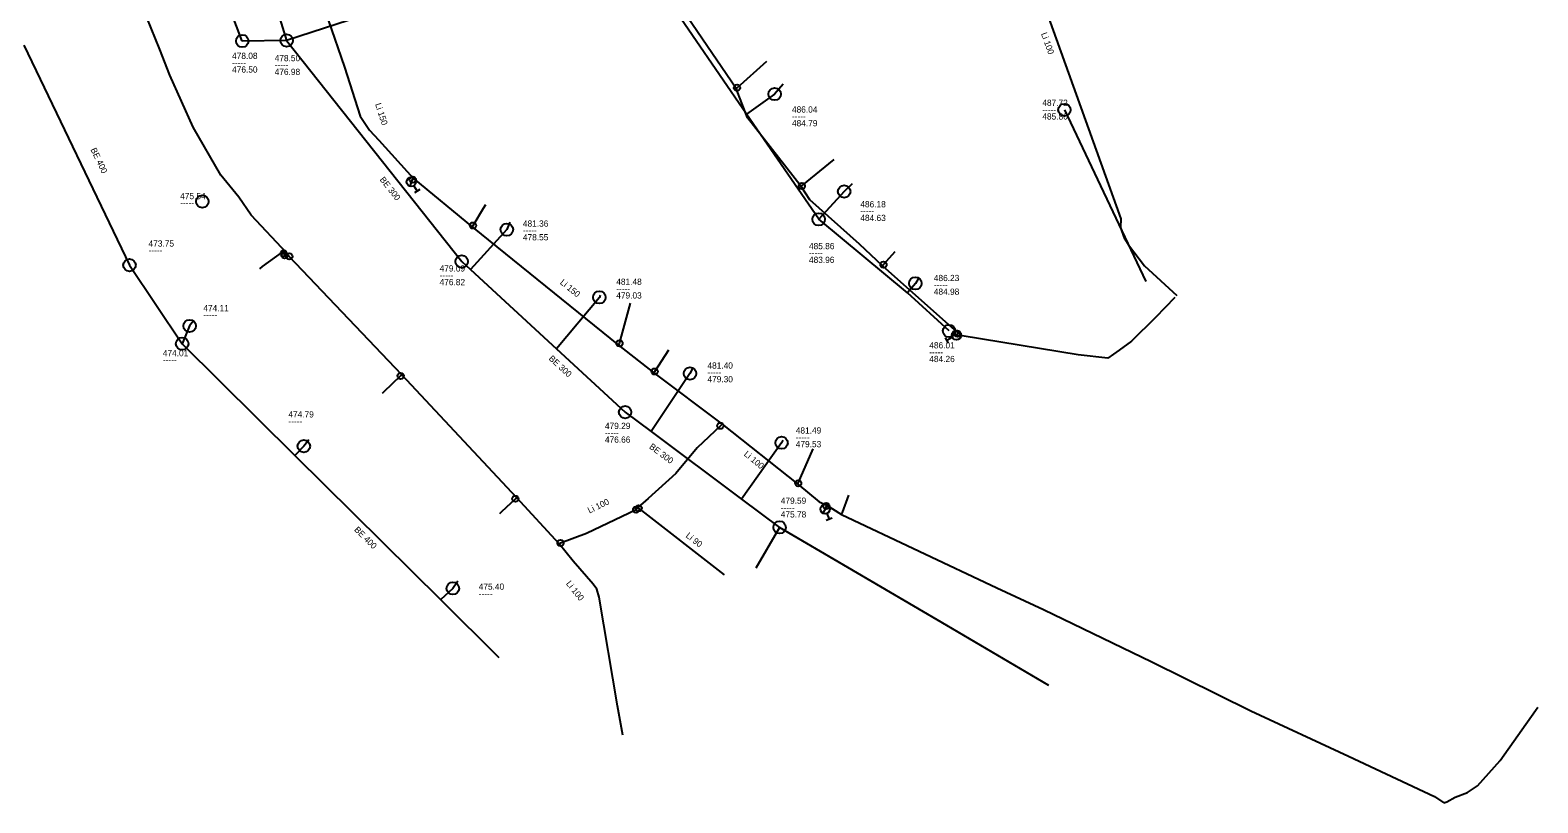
# Model space of a CAD drawing. Extents: x -685576 to -685179, y -1163336 to -1162895.
# Drawn here: x -685424.5 to -685182.3, y -1163335.7 to -1163211.6 of the extents above; entities that cross this region are included whole.
import ezdxf

# ---------------------------------------------------------------- set-up
doc = ezdxf.new("R2010")
doc.units = 0
doc.layers.add('Level 0', color=7, linetype='Continuous')

msp = doc.modelspace()

# ---------------------------------------------------------------- linework, layer by layer
at = {"layer": 'Level 0'}
for p, q in [((-685390.47, -1163213.33), (-685406.53, -1163170.83)), ((-685269.88, -1163184.54), (-685249.32, -1163241.89)), ((-685389.45, -1163193.49), (-685383.34, -1163213.24)), ((-685309.45, -1163225.05), (-685329.26, -1163196.15)), ((-685346.32, -1163201.19), (-685383.34, -1163213.24)), ((-685311.11, -1163220.95), (-685322.31, -1163204.53)), ((-685403.73, -1163214.71), (-685406.47, -1163207.84)), ((-685376.64, -1163209.9), (-685374.03, -1163217.52)), ((-685425.56, -1163214), (-685408.59, -1163249.33)), ((-685402.13, -1163218.81), (-685403.73, -1163214.71)), ((-685383.34, -1163213.24), (-685390.47, -1163213.33)), ((-685383.34, -1163213.24), (-685355.21, -1163248.74)), ((-685374.03, -1163217.52), (-685371.51, -1163225.37)), ((-685310.97, -1163220.83), (-685306.17, -1163216.55)), ((-685398.38, -1163227.18), (-685402.13, -1163218.81)), ((-685311.11, -1163220.95), (-685310.97, -1163220.83)), ((-685309.3, -1163225.68), (-685311.11, -1163220.95)), ((-685304.94, -1163221.85), (-685309.45, -1163225.05)), ((-685303.56, -1163220.24), (-685304.94, -1163221.85)), ((-685258.38, -1163224.39), (-685245.28, -1163251.95)), ((-685393.89, -1163234.85), (-685398.38, -1163227.18)), ((-685371.51, -1163225.37), (-685370.03, -1163227.64)), ((-685297.86, -1163241.96), (-685309.45, -1163225.05)), ((-685300.66, -1163236.72), (-685309.3, -1163225.68)), ((-685370.03, -1163227.64), (-685368.52, -1163229.24)), ((-685368.52, -1163229.24), (-685362.98, -1163235.41)), ((-685300.57, -1163236.6), (-685295.39, -1163232.34)), ((-685391.01, -1163238.41), (-685393.89, -1163234.85)), ((-685363.05, -1163235.25), (-685363.57, -1163236.66)), ((-685363.08, -1163235.58), (-685363.31, -1163235.95)), ((-685362.98, -1163235.41), (-685363.08, -1163235.58)), ((-685362.98, -1163235.41), (-685353.47, -1163243.25)), ((-685362.91, -1163236.59), (-685362.39, -1163237.44)), ((-685300.66, -1163236.72), (-685300.57, -1163236.6)), ((-685299.28, -1163238.81), (-685300.66, -1163236.72)), ((-685292.49, -1163236.25), (-685293.76, -1163237.5)), ((-685389.06, -1163241.28), (-685391.01, -1163238.41)), ((-685361.96, -1163237.17), (-685362.81, -1163237.7)), ((-685291.29, -1163245.96), (-685299.28, -1163238.81)), ((-685293.76, -1163237.5), (-685297.86, -1163241.96)), ((-685383.31, -1163247.4), (-685389.06, -1163241.28)), ((-685353.38, -1163242.96), (-685351.69, -1163240.16)), ((-685351.69, -1163240.16), (-685351.34, -1163239.61)), ((-685283.57, -1163253.78), (-685297.86, -1163241.96)), ((-685249.32, -1163241.89), (-685249.35, -1163243.29)), ((-685347.96, -1163243.62), (-685353.8, -1163250.04)), ((-685353.47, -1163243.25), (-685353.38, -1163242.96)), ((-685353.47, -1163243.25), (-685330.04, -1163262.19)), ((-685347.49, -1163242.45), (-685347.96, -1163243.62)), ((-685249.35, -1163243.29), (-685248.84, -1163244.81)), ((-685287.62, -1163249.46), (-685291.29, -1163245.96)), ((-685248.84, -1163244.81), (-685248.06, -1163246.08)), ((-685248.06, -1163246.08), (-685245.49, -1163249.43)), ((-685384.01, -1163247.19), (-685387.27, -1163249.55)), ((-685383.83, -1163247.45), (-685384.01, -1163247.19)), ((-685383.57, -1163247.66), (-685383.83, -1163247.45)), ((-685383.67, -1163247.77), (-685383.57, -1163247.66)), ((-685383.57, -1163247.66), (-685383.31, -1163247.4)), ((-685383.31, -1163247.4), (-685382.91, -1163247.92)), ((-685364.83, -1163266.94), (-685382.91, -1163247.92)), ((-685355.21, -1163248.74), (-685353.8, -1163250.04)), ((-685287.45, -1163249.24), (-685285.59, -1163247.15)), ((-685408.59, -1163249.33), (-685400.12, -1163261.95)), ((-685387.27, -1163249.55), (-685387.72, -1163249.9)), ((-685353.8, -1163250.04), (-685340, -1163262.77)), ((-685287.62, -1163249.46), (-685287.45, -1163249.24)), ((-685275.49, -1163260.19), (-685287.62, -1163249.46)), ((-685281.86, -1163251.51), (-685282.33, -1163252.26)), ((-685245.49, -1163249.43), (-685240.34, -1163254.18)), ((-685282.33, -1163252.26), (-685283.57, -1163253.78)), ((-685276.91, -1163259.9), (-685283.57, -1163253.78)), ((-685333.1, -1163254.5), (-685340, -1163262.77)), ((-685332.97, -1163254.17), (-685333.1, -1163254.5)), ((-685329.86, -1163261.89), (-685328.11, -1163255.43)), ((-685240.63, -1163254.54), (-685243.77, -1163257.74)), ((-685398.28, -1163258.25), (-685398.92, -1163259.09)), ((-685243.77, -1163257.74), (-685247.6, -1163261.56)), ((-685398.92, -1163259.09), (-685400.12, -1163261.95)), ((-685277.01, -1163261.88), (-685277.51, -1163261.01)), ((-685276.39, -1163260.95), (-685277.26, -1163261.45)), ((-685275.05, -1163260.85), (-685276.44, -1163260.29)), ((-685275.58, -1163260.35), (-685275.74, -1163260.57)), ((-685275.49, -1163260.19), (-685275.58, -1163260.35)), ((-685274.82, -1163260.69), (-685275.49, -1163260.19)), ((-685256.19, -1163263.72), (-685274.82, -1163260.69)), ((-685400.12, -1163261.95), (-685382.02, -1163279.88)), ((-685340, -1163262.77), (-685328.96, -1163272.95)), ((-685330.04, -1163262.19), (-685329.86, -1163261.89)), ((-685330.04, -1163262.19), (-685324.37, -1163266.65)), ((-685324.21, -1163266.41), (-685321.93, -1163262.95)), ((-685251.4, -1163264.27), (-685256.19, -1163263.72)), ((-685249.56, -1163262.98), (-685251.4, -1163264.27)), ((-685247.6, -1163261.56), (-685249.56, -1163262.98)), ((-685318.13, -1163265.94), (-685318.54, -1163266.73)), ((-685365.02, -1163267.13), (-685367.75, -1163269.74)), ((-685364.83, -1163266.94), (-685365.02, -1163267.13)), ((-685364.79, -1163266.94), (-685364.83, -1163266.94)), ((-685346.37, -1163286.69), (-685364.83, -1163266.94)), ((-685318.54, -1163266.73), (-685324.77, -1163276.07)), ((-685324.37, -1163266.65), (-685324.21, -1163266.41)), ((-685324.37, -1163266.65), (-685313.39, -1163274.86)), ((-685367.75, -1163269.74), (-685367.99, -1163269.96)), ((-685328.96, -1163272.95), (-685324.77, -1163276.07)), ((-685313.66, -1163275.14), (-685317.36, -1163278.7)), ((-685313.39, -1163274.86), (-685313.66, -1163275.14)), ((-685313.39, -1163274.86), (-685301.22, -1163284.5)), ((-685379.76, -1163277.4), (-685380.57, -1163278.41)), ((-685324.77, -1163276.07), (-685310.25, -1163286.9)), ((-685303.82, -1163277.86), (-685310.25, -1163286.9)), ((-685303.62, -1163277.45), (-685303.82, -1163277.86)), ((-685380.57, -1163278.41), (-685382.02, -1163279.88)), ((-685382.02, -1163279.88), (-685358.59, -1163303.09)), ((-685317.36, -1163278.7), (-685320.83, -1163282.81)), ((-685301.15, -1163284.36), (-685298.74, -1163278.82)), ((-685320.83, -1163282.81), (-685325.26, -1163286.83)), ((-685301.22, -1163284.5), (-685301.15, -1163284.36)), ((-685301.22, -1163284.5), (-685297.78, -1163287.36)), ((-685346.58, -1163286.86), (-685348.82, -1163288.94)), ((-685346.37, -1163286.69), (-685346.58, -1163286.86)), ((-685339.58, -1163294.07), (-685346.37, -1163286.69)), ((-685325.26, -1163286.83), (-685326.9, -1163288.26)), ((-685310.25, -1163286.9), (-685304.14, -1163291.45)), ((-685297.78, -1163287.36), (-685296.66, -1163287.81)), ((-685296.47, -1163287.87), (-685297.21, -1163289.17)), ((-685296.66, -1163287.81), (-685294.17, -1163289.38)), ((-685296.66, -1163287.81), (-685296.64, -1163288.03)), ((-685294.06, -1163289.04), (-685293, -1163286.26)), ((-685348.82, -1163288.94), (-685349.12, -1163289.26)), ((-685327.19, -1163288.62), (-685335.17, -1163292.44)), ((-685326.9, -1163288.26), (-685327.19, -1163288.62)), ((-685326.9, -1163288.26), (-685326.79, -1163288.39)), ((-685326.79, -1163288.39), (-685313.05, -1163299.09)), ((-685296.64, -1163288.03), (-685296.84, -1163288.52)), ((-685295.72, -1163289.95), (-685296.64, -1163290.33)), ((-685296.56, -1163289.21), (-685296.18, -1163290.14)), ((-685294.17, -1163289.38), (-685294.06, -1163289.04)), ((-685294.17, -1163289.38), (-685269.25, -1163301.17)), ((-685335.17, -1163292.44), (-685339.34, -1163293.97)), ((-685304.14, -1163291.45), (-685307.97, -1163297.99)), ((-685293.2, -1163297.88), (-685304.14, -1163291.45)), ((-685339.34, -1163293.97), (-685339.58, -1163294.07)), ((-685337.33, -1163296.89), (-685339.58, -1163294.07)), ((-685334.11, -1163300.6), (-685337.33, -1163296.89)), ((-685355.84, -1163300.09), (-685356.63, -1163301.25)), ((-685277.28, -1163307.23), (-685293.2, -1163297.88)), ((-685356.63, -1163301.25), (-685358.56, -1163303.06)), ((-685333.51, -1163301.35), (-685334.11, -1163300.6)), ((-685333.11, -1163302.67), (-685333.51, -1163301.35)), ((-685269.25, -1163301.17), (-685261.75, -1163304.63)), ((-685358.56, -1163303.06), (-685358.59, -1163303.09)), ((-685358.59, -1163303.09), (-685349.24, -1163312.35)), ((-685330.16, -1163320.11), (-685333.11, -1163302.67)), ((-685261.75, -1163304.63), (-685244.32, -1163313.06)), ((-685260.91, -1163316.85), (-685277.28, -1163307.23)), ((-685244.32, -1163313.06), (-685228.44, -1163320.9)), ((-685329.35, -1163324.82), (-685330.16, -1163320.11)), ((-685228.44, -1163320.9), (-685212.74, -1163328.21)), ((-685188.37, -1163328.92), (-685182.7, -1163320.88)), ((-685182.7, -1163320.88), (-685182.32, -1163320.35)), ((-685212.74, -1163328.21), (-685198.9, -1163334.66)), ((-685192.02, -1163332.97), (-685188.37, -1163328.92)), ((-685193.6, -1163334.04), (-685192.02, -1163332.97)), ((-685198.9, -1163334.66), (-685197.44, -1163335.7)), ((-685197.44, -1163335.7), (-685196.95, -1163335.55)), ((-685196.95, -1163335.55), (-685195.62, -1163334.81)), ((-685195.62, -1163334.81), (-685193.6, -1163334.04))]:
    msp.add_line(p, q, dxfattribs=at)
for centre, radius in [((-685390.47, -1163213.33), 1), ((-685383.34, -1163213.24), 1), ((-685310.97, -1163220.83), 0.5), ((-685304.94, -1163221.85), 1), ((-685258.38, -1163224.39), 1), ((-685363.31, -1163235.95), 0.75), ((-685363.08, -1163235.58), 0.5), ((-685300.57, -1163236.6), 0.5), ((-685293.76, -1163237.5), 1), ((-685396.89, -1163239.11), 1), ((-685297.86, -1163241.96), 1), ((-685353.38, -1163242.96), 0.5), ((-685347.96, -1163243.62), 1), ((-685408.59, -1163249.33), 1), ((-685383.83, -1163247.45), 0.5), ((-685383.67, -1163247.77), 0.5), ((-685382.91, -1163247.92), 0.5), ((-685355.21, -1163248.74), 1), ((-685287.45, -1163249.24), 0.5), ((-685282.33, -1163252.26), 1), ((-685333.1, -1163254.5), 1), ((-685398.92, -1163259.09), 1), ((-685276.91, -1163259.9), 1), ((-685400.12, -1163261.95), 1), ((-685275.74, -1163260.57), 0.75), ((-685275.58, -1163260.35), 0.5), ((-685329.86, -1163261.89), 0.5), ((-685324.21, -1163266.41), 0.5), ((-685318.54, -1163266.73), 1), ((-685365.02, -1163267.13), 0.5), ((-685328.96, -1163272.95), 1), ((-685313.66, -1163275.14), 0.5), ((-685380.57, -1163278.41), 1), ((-685303.82, -1163277.86), 1), ((-685301.15, -1163284.36), 0.5), ((-685346.58, -1163286.86), 0.5), ((-685326.79, -1163288.39), 0.5), ((-685296.84, -1163288.52), 0.75), ((-685296.64, -1163288.03), 0.5), ((-685327.19, -1163288.62), 0.5), ((-685304.14, -1163291.45), 1), ((-685339.34, -1163293.97), 0.5), ((-685356.63, -1163301.25), 1)]:
    msp.add_circle(centre, radius, dxfattribs=at)

# ---------------------------------------------------------------- texts
for s, rotation, p in [('Li 100', 289.723, (-685262.16, -1163212.15)), ('Li 150', 287.798, (-685369.13, -1163223.47)), ('BE 400', 295.657, (-685414.87, -1163230.76)), ('BE 300', 308.393, (-685368.45, -1163235.62)), ('Li 150', 321.049, (-685339.52, -1163252.27)), ('BE 300', 317.314, (-685341.32, -1163264.44)), ('BE 300', 323.3, (-685325.18, -1163278.68)), ('Li 100', 320.26, (-685309.96, -1163279.83)), ('Li 100', 25.58, (-685334.69, -1163289.24)), ('BE 400', 315.273, (-685372.56, -1163291.92)), ('Li 90', 322.09, (-685319.31, -1163292.95)), ('Li 100', 308.66, (-685338.52, -1163300.51))]:
    msp.add_text(s, height=1, rotation=rotation, dxfattribs=at).set_placement(p)
for s, p in [('478.08', (-685392.1, -1163216.2)), ('476.50', (-685392.1, -1163218.4)), ('-----', (-685392.1, -1163217.3)), ('478.50', (-685385.26, -1163216.57)), ('-----', (-685385.26, -1163217.67)), ('476.98', (-685385.26, -1163218.77)), ('486.04', (-685302.15, -1163224.82)), ('487.72', (-685261.93, -1163223.74)), ('485.80', (-685261.93, -1163225.94)), ('-----', (-685261.93, -1163224.84)), ('484.79', (-685302.15, -1163227.02)), ('-----', (-685302.15, -1163225.92)), ('475.54', (-685400.44, -1163238.73)), ('-----', (-685400.44, -1163239.83)), ('486.18', (-685291.17, -1163240.04)), ('484.63', (-685291.17, -1163242.24)), ('-----', (-685291.17, -1163241.14)), ('481.36', (-685345.38, -1163243.15)), ('478.55', (-685345.38, -1163245.35)), ('-----', (-685345.38, -1163244.25)), ('473.75', (-685405.52, -1163246.35)), ('485.86', (-685299.42, -1163246.77)), ('-----', (-685405.52, -1163247.45)), ('483.96', (-685299.42, -1163248.97)), ('-----', (-685299.42, -1163247.87)), ('479.09', (-685358.76, -1163250.35)), ('476.82', (-685358.76, -1163252.55)), ('-----', (-685358.76, -1163251.45)), ('481.48', (-685330.38, -1163252.49)), ('486.23', (-685279.36, -1163251.89)), ('479.03', (-685330.38, -1163254.69)), ('-----', (-685330.38, -1163253.59)), ('484.98', (-685279.36, -1163254.09)), ('-----', (-685279.36, -1163252.99)), ('474.11', (-685396.72, -1163256.73)), ('-----', (-685396.72, -1163257.83)), ('474.01', (-685403.23, -1163263.96)), ('486.01', (-685280.09, -1163262.7)), ('-----', (-685280.09, -1163263.8)), ('-----', (-685403.23, -1163265.06)), ('481.40', (-685315.73, -1163265.95)), ('484.26', (-685280.09, -1163264.9)), ('479.30', (-685315.73, -1163268.15)), ('-----', (-685315.73, -1163267.05)), ('474.79', (-685383.06, -1163273.8)), ('-----', (-685383.06, -1163274.9)), ('479.29', (-685332.2, -1163275.65)), ('481.49', (-685301.54, -1163276.38)), ('476.66', (-685332.2, -1163277.85)), ('-----', (-685332.2, -1163276.75)), ('479.53', (-685301.54, -1163278.58)), ('-----', (-685301.54, -1163277.48)), ('479.59', (-685303.95, -1163287.66)), ('475.78', (-685303.95, -1163289.86)), ('-----', (-685303.95, -1163288.76)), ('475.40', (-685352.48, -1163301.47)), ('-----', (-685352.48, -1163302.57))]:
    msp.add_text(s, height=1, dxfattribs=at).set_placement(p)

doc.saveas('drawing.dxf')
